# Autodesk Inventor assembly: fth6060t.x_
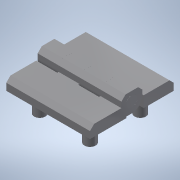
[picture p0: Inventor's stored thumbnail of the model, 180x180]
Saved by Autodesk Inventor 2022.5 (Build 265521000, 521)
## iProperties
Part Number: fth6060t.x_
Material: 一般
Document SubType Name: Assembly
Designer: ImaoCorp
Sending System: SOLIDWORKS 2017-2017317
MC: AMD64
MC_MODEL: Intel64 Family 6 Model 60 Stepping 3, GenuineIntel
OS: Windows_NT
FRU: Parasolid Version 29.0, build 201,  4-17-2017
FORMAT: text
GUISE: transmit
KEY: fth6060t
FILE: fth6060t.x_t
DATE: Mon May 13 14:28:30 2019
Author: ImaoCorp
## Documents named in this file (4)
- X:\14_SW2022-Inv2022\00_全2023-1023新製品(TCC)まで\f\fth6060t\FTH6060T.iam
- X:\14_SW2022-Inv2022\00_全2023-1023新製品(TCC)まで\f\fth6060t\fth6060t_01.ipt
- X:\14_SW2022-Inv2022\00_全2023-1023新製品(TCC)まで\f\fth6060t\fth6060t_02.ipt
- X:\14_SW2022-Inv2022\00_全2023-1023新製品(TCC)まで\f\fth6060t\fth6060t_03.ipt
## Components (3 placed, 3 different names)
1. fth6060t_01
2. fth6060t_02
3. fth6060t_03
